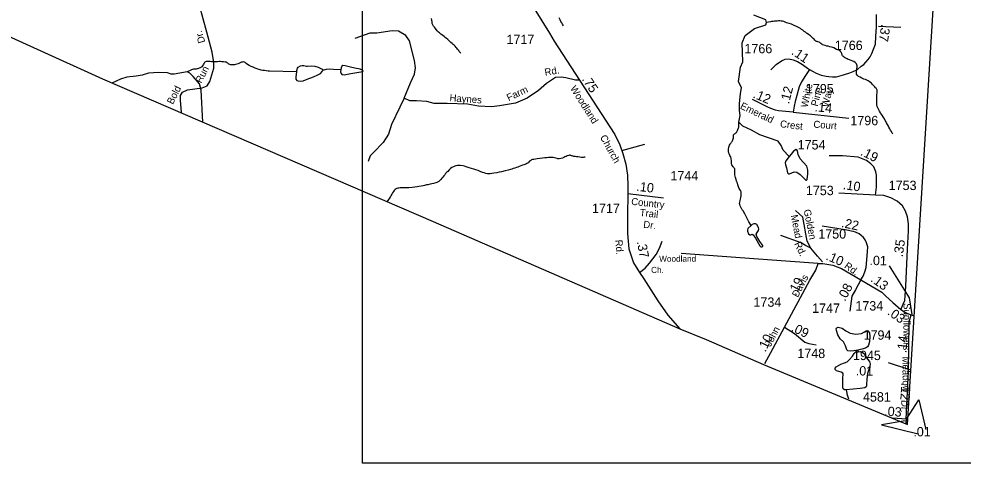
# Model space of a CAD drawing. Extents: x 2056842 to 2160602, y 826753 to 1016856.
# Drawn here: x 2121968 to 2134581, y 826753 to 832686 of the extents above; entities that cross this region are included whole.
import ezdxf

# ---------------------------------------------------------------- set-up
doc = ezdxf.new("R2010")
doc.units = 0
for name, color, linetype in [('Exist Boundary Political CountyLine', 7, 'Continuous'), ('Exist Cultural Church with Cemetery Label', 7, 'Continuous'), ('Exist Hydrographic Creek Single Shore', 7, 'Continuous'), ('Exist Hydrographic Misc Water Feature', 7, 'Continuous'), ('Exist Road Non-System Type 51', 7, 'Continuous'), ('Exist Road Non-System Type 51 Label', 7, 'Continuous'), ('Exist Road Secondary Mileage Hundredths English Label', 7, 'Continuous'), ('Exist Road Secondary Type 51 Attributed', 7, 'Continuous'), ('Exist Road Secondary Type 51 Label', 7, 'Continuous'), ('Exist Road Secondary Type 51 Number Label', 7, 'Continuous'), ('Map Preparation Inset Cut Line', 7, 'Continuous')]:
    doc.layers.add(name, color=color, linetype=linetype)

msp = doc.modelspace()

# ---------------------------------------------------------------- linework, layer by layer
at = {"layer": 'Exist Boundary Political CountyLine'}
for points in [[(2133839, 827270), (2134339, 835334), (2134342, 841203), (2134508, 848638), (2140998, 864498)], [(2133839, 827270), (2134339, 835334), (2134342, 841203), (2134508, 848638)], [(2102162, 841869), (2110170, 837921), (2110937, 837538), (2113401, 836382), (2113845, 836166), (2114325, 835934), (2116216, 835033), (2117013, 834658), (2117168, 834573), (2123083, 831884), (2127502, 829978), (2130799, 828548), (2131147, 828402), (2131915, 828068), (2133839, 827270)]]:
    msp.add_lwpolyline(points, dxfattribs=at)
at = {"layer": 'Exist Hydrographic Creek Single Shore'}
for points in [[(2127710, 832397), (2127697, 832409), (2127675, 832429), (2127663, 832440), (2127655, 832446), (2127647, 832452), (2127633, 832464), (2127613, 832476), (2127603, 832484), (2127587, 832498), (2127575, 832510), (2127557, 832529), (2127534, 832556), (2127518, 832577), (2127508, 832591), (2127496, 832609), (2127490, 832623), (2127490, 832631), (2127488, 832647), (2127483, 832670), (2127479, 832693)], [(2129243, 832594), (2129229, 832617), (2129219, 832634), (2129208, 832652), (2129198, 832674), (2129184, 832702)], [(2132256, 830847), (2132179, 830931), (2132152, 830994), (2132110, 831051), (2131864, 831136), (2131756, 831199), (2131639, 831253), (2131584, 831308), (2131602, 831394), (2131592, 831464), (2131596, 831552), (2131608, 831690), (2131620, 831766), (2131579, 831850), (2131607, 832043), (2131637, 832112), (2131629, 832366), (2131669, 832463), (2131795, 832557), (2131945, 832609), (2131954, 832640), (2131944, 832675), (2131786, 832734)], [(2132633, 832384), (2132625, 832385), (2132616, 832388), (2132611, 832392), (2132607, 832396), (2132601, 832404), (2132591, 832414), (2132580, 832424), (2132568, 832435), (2132560, 832444), (2132542, 832459), (2132530, 832467), (2132516, 832477), (2132500, 832489), (2132488, 832497), (2132474, 832509), (2132460, 832520), (2132440, 832535), (2132424, 832546), (2132407, 832556), (2132383, 832570), (2132354, 832586), (2132323, 832599), (2132289, 832614), (2132257, 832624), (2132223, 832634), (2132203, 832643), (2132187, 832650), (2132169, 832656), (2132153, 832658), (2132133, 832660), (2132117, 832660), (2132097, 832658), (2132061, 832655), (2132044, 832653), (2132023, 832651), (2132009, 832649), (2131954, 832640)], [(2127871, 832230), (2127855, 832248), (2127851, 832252), (2127843, 832264), (2127835, 832274), (2127826, 832284), (2127817, 832295), (2127808, 832306), (2127794, 832321), (2127784, 832334), (2127770, 832345), (2127754, 832359), (2127740, 832371), (2127724, 832385), (2127710, 832397)], [(2133644, 831149), (2133633, 831162), (2133623, 831181), (2133613, 831198), (2133603, 831217), (2133591, 831241), (2133585, 831255), (2133572, 831275), (2133560, 831296), (2133552, 831310), (2133542, 831328), (2133530, 831352), (2133514, 831377), (2133499, 831400), (2133483, 831423), (2133477, 831433), (2133465, 831452), (2133454, 831471), (2133443, 831497), (2133434, 831517), (2133430, 831537), (2133428, 831547), (2133428, 831562), (2133430, 831577), (2133431, 831611), (2133431, 831643), (2133431, 831663), (2133435, 831707), (2133435, 831722), (2133432, 831735), (2133428, 831745), (2133418, 831759), (2133412, 831767), (2133404, 831777), (2133394, 831788), (2133382, 831803), (2133368, 831816), (2133356, 831828), (2133344, 831836), (2133328, 831848), (2133315, 831857), (2133296, 831867), (2133276, 831875), (2133253, 831883), (2133227, 831894), (2133205, 831906), (2133183, 831919), (2133167, 831933), (2133159, 831947), (2133156, 831960), (2133156, 831971), (2133156, 831979), (2133158, 832001), (2133160, 832013), (2133162, 832027), (2133164, 832035), (2133166, 832047), (2133166, 832060), (2133162, 832073), (2133157, 832084), (2133149, 832094), (2133139, 832105), (2133123, 832115), (2133109, 832121), (2133087, 832129), (2133063, 832138), (2133047, 832146), (2133031, 832152), (2133013, 832162), (2132999, 832170), (2132986, 832178), (2132976, 832187), (2132971, 832193), (2132967, 832201), (2132964, 832207), (2132962, 832215), (2132960, 832223), (2132956, 832235), (2132950, 832244), (2132942, 832254), (2132934, 832261), (2132922, 832267), (2132907, 832273), (2132894, 832279), (2132876, 832286), (2132854, 832298), (2132839, 832304), (2132821, 832309), (2132802, 832314), (2132778, 832320), (2132760, 832323), (2132738, 832329), (2132719, 832335), (2132703, 832341), (2132695, 832347), (2132681, 832359), (2132669, 832369), (2132657, 832376), (2132641, 832382), (2132633, 832384)], [(2131749, 829925), (2131721, 829974), (2131703, 830010), (2131690, 830031), (2131676, 830064), (2131666, 830084), (2131641, 830123), (2131632, 830137), (2131622, 830152), (2131601, 830191), (2131597, 830206), (2131595, 830221), (2131597, 830239), (2131601, 830257), (2131606, 830282), (2131612, 830301), (2131616, 830321), (2131618, 830347), (2131618, 830365), (2131615, 830375), (2131607, 830395), (2131599, 830409), (2131591, 830421), (2131581, 830443), (2131573, 830469), (2131566, 830491), (2131556, 830521), (2131550, 830540), (2131542, 830569), (2131538, 830584), (2131533, 830602), (2131531, 830622), (2131531, 830642), (2131532, 830657), (2131533, 830669), (2131531, 830682), (2131525, 830692), (2131519, 830700), (2131511, 830710), (2131501, 830724), (2131494, 830736), (2131489, 830747), (2131486, 830762), (2131486, 830772), (2131486, 830784), (2131486, 830796), (2131484, 830811), (2131482, 830824), (2131479, 830835), (2131474, 830849), (2131467, 830862), (2131461, 830876), (2131453, 830893), (2131446, 830917), (2131446, 830930), (2131446, 830945), (2131452, 830974), (2131456, 830986), (2131462, 831000), (2131468, 831012), (2131476, 831022), (2131483, 831030), (2131489, 831039), (2131496, 831047), (2131501, 831057), (2131507, 831071), (2131511, 831084), (2131513, 831098), (2131513, 831110), (2131513, 831119), (2131513, 831126), (2131513, 831130), (2131514, 831136), (2131517, 831142), (2131523, 831146), (2131529, 831150), (2131535, 831154), (2131541, 831160), (2131547, 831164), (2131554, 831170), (2131558, 831177), (2131568, 831195), (2131573, 831207), (2131581, 831233), (2131584, 831241), (2131587, 831267), (2131584, 831308)]]:
    msp.add_lwpolyline(points, dxfattribs=at)
at = {"layer": 'Exist Hydrographic Misc Water Feature'}
for points in [[(2125676, 831978), (2125317, 831989), (2125299, 831990), (2125271, 831993), (2125251, 831995), (2125228, 831999), (2125203, 832002), (2125176, 832009), (2125158, 832015), (2125136, 832024), (2125122, 832030), (2125099, 832041), (2125072, 832052), (2125046, 832063), (2125024, 832075), (2125006, 832089), (2124990, 832103), (2124980, 832110), (2124970, 832113), (2124962, 832113), (2124950, 832110), (2124943, 832108), (2124934, 832105), (2124916, 832094), (2124896, 832086), (2124879, 832080), (2124862, 832076), (2124847, 832074), (2124830, 832072), (2124812, 832071), (2124796, 832071), (2124784, 832075), (2124772, 832082), (2124760, 832093), (2124750, 832100), (2124742, 832107), (2124734, 832111), (2124724, 832110), (2124700, 832112), (2124678, 832114), (2124658, 832116), (2124642, 832116), (2124620, 832114), (2124596, 832113), (2124568, 832113), (2124542, 832113), (2124522, 832115), (2124500, 832116), (2124482, 832117), (2124469, 832117), (2124459, 832113), (2124452, 832107), (2124448, 832102), (2124444, 832096), (2124436, 832082), (2124428, 832072), (2124411, 832047), (2124405, 832042), (2124399, 832038), (2124390, 832034), (2124377, 832027), (2124365, 832023), (2124350, 832018), (2124338, 832015), (2124326, 832015), (2124312, 832013), (2124299, 832013), (2124287, 832011), (2124272, 832007), (2124257, 831998), (2124215, 831977)], [(2125676, 831978), (2125667, 831914), (2125668, 831883), (2125680, 831864), (2125697, 831857), (2125728, 831855), (2125765, 831860), (2125820, 831880), (2125904, 831913), (2125960, 831939), (2125995, 831959), (2126018, 831983), (2126028, 832001)], [(2125676, 831978), (2125689, 832026), (2125698, 832040), (2125729, 832059), (2125754, 832066), (2125775, 832062), (2125808, 832054), (2125824, 832055), (2125873, 832061), (2125921, 832056), (2125966, 832043), (2126017, 832016), (2126028, 832001)], [(2126028, 832001), (2126075, 832014), (2126112, 832018), (2126170, 832016), (2126269, 832010)], [(2126269, 832010), (2126266, 831977), (2126271, 831955), (2126283, 831943), (2126311, 831937), (2126400, 831958), (2126484, 831972), (2126537, 831980), (2126563, 831984), (2126565, 831992), (2126559, 832000), (2126525, 832014), (2126457, 832029), (2126396, 832040), (2126326, 832061), (2126297, 832063), (2126283, 832057), (2126272, 832031), (2126269, 832010)], [(2124424, 831305), (2124405, 831733), (2124379, 831818), (2124296, 831915), (2124252, 831961), (2124215, 831977), (2124044, 831948), (2124002, 831949), (2123951, 831967), (2123834, 831971), (2123699, 831962), (2123613, 831936), (2123535, 831922), (2123408, 831907), (2123324, 831882), (2123208, 831830)], [(2129533, 830843), (2129527, 830840), (2129517, 830838), (2129507, 830837), (2129496, 830836), (2129482, 830836), (2129461, 830838), (2129435, 830842), (2129415, 830844), (2129397, 830847), (2129383, 830850), (2129371, 830853), (2129359, 830856), (2129350, 830859), (2129341, 830862), (2129333, 830865), (2129322, 830865), (2129314, 830863), (2129293, 830855), (2129277, 830849), (2129262, 830843), (2129247, 830836), (2129229, 830828), (2129209, 830822), (2129185, 830818), (2129167, 830819), (2129159, 830822), (2129141, 830825), (2129121, 830829), (2129105, 830833), (2129089, 830835), (2129065, 830834), (2129041, 830834), (2129019, 830832), (2128993, 830830), (2128963, 830826), (2128927, 830822), (2128893, 830818), (2128867, 830813), (2128845, 830809), (2128828, 830807), (2128817, 830803), (2128805, 830796), (2128789, 830784), (2128780, 830774), (2128772, 830766), (2128766, 830760), (2128754, 830754), (2128740, 830748), (2128714, 830739), (2128696, 830733), (2128674, 830724), (2128652, 830715), (2128632, 830706), (2128616, 830701), (2128594, 830694), (2128572, 830686), (2128551, 830680), (2128533, 830674), (2128503, 830666), (2128463, 830657), (2128415, 830645), (2128385, 830638), (2128351, 830632), (2128312, 830624), (2128285, 830620), (2128265, 830616), (2128247, 830615), (2128226, 830617), (2128207, 830621), (2128183, 830628), (2128159, 830636), (2128131, 830649), (2128101, 830660), (2128071, 830672), (2128047, 830680), (2128013, 830690), (2127985, 830699), (2127945, 830712), (2127921, 830720), (2127904, 830724), (2127862, 830730), (2127842, 830730), (2127828, 830730), (2127805, 830725), (2127793, 830721), (2127774, 830712), (2127752, 830700), (2127735, 830687), (2127717, 830668), (2127697, 830648), (2127685, 830638), (2127669, 830620), (2127656, 830604), (2127644, 830588), (2127630, 830572), (2127618, 830557), (2127604, 830541), (2127591, 830528), (2127577, 830516)], [(2132256, 830847), (2132213, 830789), (2132206, 830765), (2132208, 830739), (2132223, 830696), (2132236, 830628), (2132247, 830618), (2132262, 830617), (2132325, 830643), (2132358, 830641), (2132406, 830610), (2132479, 830531), (2132488, 830531), (2132499, 830541), (2132506, 830617), (2132508, 830665), (2132494, 830718), (2132447, 830769), (2132405, 830819), (2132379, 830873), (2132370, 830926), (2132362, 830936), (2132350, 830940), (2132317, 830921), (2132283, 830878), (2132256, 830847)], [(2127577, 830516), (2127567, 830509), (2127553, 830503), (2127537, 830497), (2127507, 830488), (2127485, 830485), (2127461, 830478), (2127431, 830472), (2127415, 830468), (2127387, 830461), (2127367, 830458), (2127341, 830453), (2127311, 830447), (2127288, 830443), (2127258, 830437), (2127222, 830432), (2127178, 830430), (2127148, 830429), (2127111, 830429), (2127077, 830429), (2127061, 830429), (2127043, 830426), (2127029, 830424), (2127018, 830421), (2127008, 830416), (2126996, 830408), (2126986, 830400), (2126980, 830394), (2126971, 830382), (2126960, 830364), (2126951, 830344), (2126943, 830332), (2126931, 830312), (2126919, 830291), (2126907, 830275), (2126895, 830259), (2126884, 830244)], [(2131749, 829925), (2131707, 829885), (2131701, 829870), (2131701, 829852), (2131716, 829816), (2131734, 829801), (2131745, 829801), (2131765, 829809), (2131776, 829802), (2131808, 829758), (2131865, 829654), (2131881, 829642), (2131895, 829641), (2131905, 829651), (2131904, 829661), (2131864, 829711), (2131824, 829778), (2131818, 829810), (2131829, 829832), (2131846, 829858), (2131853, 829880), (2131848, 829901), (2131824, 829940), (2131809, 829947), (2131786, 829949), (2131765, 829941), (2131749, 829925)], [(2133174, 828263), (2133121, 828251), (2133075, 828246), (2133041, 828252), (2133030, 828265), (2133008, 828321), (2132984, 828372), (2132938, 828415), (2132910, 828465), (2132891, 828525), (2132887, 828551), (2132893, 828561), (2132913, 828568), (2132964, 828554), (2133015, 828520), (2133071, 828487), (2133149, 828476), (2133222, 828485), (2133296, 828523), (2133308, 828519), (2133330, 828493), (2133336, 828443), (2133333, 828379), (2133318, 828327), (2133303, 828306), (2133277, 828288), (2133227, 828277), (2133174, 828263)], [(2133020, 827733), (2132996, 827733), (2132980, 827743), (2132974, 827754), (2132973, 827783), (2132976, 827889), (2132978, 827943), (2132973, 827955), (2132954, 827967), (2132892, 827985), (2132873, 828005), (2132872, 828020), (2132884, 828039), (2132946, 828075), (2132998, 828092), (2133031, 828107), (2133064, 828135), (2133104, 828181), (2133124, 828219), (2133145, 828235), (2133179, 828241)], [(2133179, 828241), (2133210, 828242), (2133235, 828234), (2133267, 828208), (2133286, 828168), (2133306, 828142), (2133331, 828109), (2133339, 828076), (2133336, 828049), (2133320, 828002), (2133306, 827949), (2133294, 827872), (2133292, 827801), (2133292, 827783), (2133287, 827771), (2133268, 827757), (2133207, 827749), (2133020, 827733)], [(2133174, 828263), (2133179, 828241)], [(2133020, 827733), (2133029, 827687), (2133030, 827677), (2133033, 827667), (2133037, 827653), (2133041, 827639), (2133051, 827615), (2133053, 827610)]]:
    msp.add_lwpolyline(points, dxfattribs=at)
at = {"layer": 'Exist Road Non-System Type 51'}
for p, q in [((2133451, 832587), (2133750, 832575)), ((2130023, 830928), (2130328, 831012))]:
    msp.add_line(p, q, dxfattribs=at)
for points in [[(2124138, 831434), (2124125, 831599), (2124127, 831661), (2124152, 831707), (2124219, 831740), (2124414, 831765), (2124482, 831794), (2124520, 831848), (2124571, 832030), (2124573, 832103), (2124548, 832240), (2124477, 832510), (2124382, 832867)], [(2127116, 831628), (2127200, 831831), (2127252, 831947), (2127267, 832033), (2127254, 832130), (2127186, 832392), (2127138, 832463), (2127038, 832521), (2126955, 832529), (2126751, 832495), (2126655, 832495), (2126456, 832424)], [(2129459, 831867), (2129404, 831868), (2129275, 831900), (2129211, 831906), (2129134, 831904), (2129016, 831825), (2128910, 831729), (2128758, 831629), (2128600, 831561), (2128388, 831527), (2128280, 831511), (2128106, 831521), (2127959, 831546), (2127691, 831557), (2127515, 831558), (2127417, 831583), (2127280, 831591), (2127191, 831591), (2127116, 831628)], [(2127116, 831628), (2127055, 831509), (2126947, 831274), (2126905, 831145), (2126832, 831036), (2126703, 830903), (2126659, 830859), (2126634, 830780)], [(2132549, 829622), (2132497, 829717), (2132439, 830039), (2132341, 830125)], [(2132549, 829622), (2132476, 829659), (2132416, 829694), (2132146, 829792)], [(2130257, 829301), (2130332, 829356), (2130391, 829424), (2130481, 829538), (2130526, 829622), (2130562, 829717)], [(2132701, 829443), (2132634, 829518), (2132549, 829622)], [(2132644, 829417), (2132214, 829451), (2130813, 829552)]]:
    msp.add_lwpolyline(points, dxfattribs=at)
at = {"layer": 'Exist Road Secondary Mileage Hundredths English Label'}
msp.add_line((2133868, 827999), (2133585, 828092), dxfattribs=at)
for points in [[(2133902, 828740), (2133864, 828961), (2133599, 829387)], [(2133830, 827350), (2133989, 827600), (2134083, 827204)], [(2133808, 827317), (2133491, 827262), (2133982, 827145)]]:
    msp.add_lwpolyline(points, dxfattribs=at)
at = {"layer": 'Exist Road Secondary Type 51 Attributed'}
for p, q in [((2132309, 831439), (2133056, 831359)), ((2130101, 830354), (2130578, 830297)), ((2133410, 830334), (2132920, 830360)), ((2133821, 827341), (2133850, 827979)), ((2133821, 827341), (2133641, 827352)), ((2133821, 827341), (2133817, 827280))]:
    msp.add_line(p, q, dxfattribs=at)
for points in [[(2128273, 833799), (2128362, 833671), (2128458, 833532), (2128526, 833413), (2128623, 833239), (2128714, 833077), (2128790, 832933), (2128851, 832826), (2129057, 832497), (2129120, 832391), (2129459, 831867), (2129928, 831143), (2129996, 831002), (2130037, 830889), (2130074, 830745), (2130099, 830600), (2130103, 830454), (2130101, 830354)], [(2132531, 832012), (2132571, 831986), (2132619, 831960), (2132686, 831933), (2132750, 831920), (2132789, 831916), (2132835, 831911), (2132892, 831914), (2132952, 831929), (2132998, 831943), (2133069, 831968), (2133114, 831985), (2133172, 832012), (2133220, 832054), (2133253, 832077), (2133281, 832108), (2133315, 832142), (2133339, 832180), (2133364, 832222), (2133385, 832283), (2133409, 832349), (2133417, 832449), (2133426, 832582), (2133424, 832744)], [(2132014, 832008), (2132084, 832079), (2132154, 832124), (2132203, 832148), (2132255, 832154), (2132311, 832140), (2132367, 832116), (2132435, 832075), (2132504, 832029), (2132531, 832012)], [(2132531, 832012), (2132466, 831915), (2132454, 831894), (2132423, 831845), (2132393, 831781), (2132377, 831732), (2132359, 831665), (2132339, 831583), (2132326, 831521), (2132309, 831439)], [(2132309, 831439), (2132113, 831459), (2132074, 831469), (2132015, 831489), (2131964, 831511), (2131766, 831611)], [(2133410, 830334), (2133425, 830437), (2133425, 830531), (2133425, 830598), (2133414, 830645), (2133389, 830712), (2133348, 830751), (2133291, 830797), (2133179, 830838), (2132971, 830855), (2132790, 830859)], [(2130101, 830354), (2130096, 830060), (2130098, 829821), (2130118, 829615), (2130177, 829427), (2130257, 829301), (2130317, 829213), (2130503, 828919), (2130637, 828729), (2130799, 828548)], [(2133749, 828806), (2133782, 828875), (2133802, 828925), (2133808, 828988), (2133814, 829118), (2133839, 829611), (2133853, 829853), (2133850, 829951), (2133838, 830044), (2133811, 830116), (2133770, 830190), (2133699, 830253), (2133618, 830298), (2133521, 830329), (2133410, 830334)], [(2133217, 829201), (2133248, 829252), (2133270, 829307), (2133285, 829367), (2133297, 829468), (2133306, 829581), (2133307, 829643), (2133291, 829693), (2133273, 829735), (2133250, 829767), (2133220, 829795), (2133192, 829816), (2133145, 829837), (2133111, 829848), (2133006, 829867), (2132697, 829918)], [(2132197, 828569), (2132533, 829197), (2132612, 829331), (2132644, 829417), (2132706, 829420), (2132843, 829399), (2132956, 829351), (2133217, 829201)], [(2133217, 829201), (2133142, 829067), (2133095, 828982), (2133070, 828782)], [(2133217, 829201), (2133495, 829035), (2133551, 828982), (2133643, 828896), (2133749, 828806)], [(2133749, 828806), (2133783, 828781), (2133830, 828754), (2133887, 828732)], [(2133850, 827979), (2133861, 828616), (2133868, 828670), (2133887, 828732)], [(2133887, 828732), (2133929, 828720)], [(2131934, 828084), (2132015, 828231), (2132197, 828569)], [(2132197, 828569), (2132329, 828485), (2132469, 828368), (2132520, 828349), (2132619, 828334)], [(2133850, 827979), (2133883, 827978)], [(2133821, 827341), (2133844, 827338)]]:
    msp.add_lwpolyline(points, dxfattribs=at)
at = {"layer": 'Map Preparation Inset Cut Line'}
msp.add_lwpolyline([(2126559, 840801), (2135708, 840801), (2135708, 826753), (2126559, 826753)], close=True, dxfattribs=at)

# ---------------------------------------------------------------- texts
at = {"layer": 'Exist Cultural Church with Cemetery Label'}
for s, p in [('Woodland', (2130521, 829442)), ('Ch.', (2130413, 829292))]:
    msp.add_text(s, height=82, dxfattribs=at).set_placement(p)
at = {"layer": 'Exist Road Non-System Type 51 Label'}
for s, rotation, p in [('Dr.', 107.6445, (2124459, 832378)), ('Run', 62.2527, (2124403, 831819)), ('Rd.', 10.1274, (2128999, 831925)), ('Bold', 62.9967, (2124024, 831536)), ('Farm', 25.3847, (2128511, 831585)), ('Haynes', 355.8284, (2127719, 831587)), ('Golden', 281.2431, (2132451, 830133)), ('Mead', 281.2431, (2132278, 830060)), ('Rd.', 295.4414, (2132323, 829683))]:
    msp.add_text(s, height=95, rotation=rotation, dxfattribs=at).set_placement(p)
at = {"layer": 'Exist Road Secondary Mileage Hundredths English Label'}
for s, rotation, p in [('.37', 260.9065, (2133490, 832622)), ('.11', 325.8265, (2132279, 832220)), ('.75', 302.8898, (2129484, 831881)), ('.12', 75.7697, (2132255, 831543)), ('.12', 336.791, (2131765, 831638)), ('.14', 353.9239, (2132594, 831454)), ('.19', 333.4437, (2133199, 830872)), ('.10', 353.1624, (2130212, 830391)), ('.10', 351.6774, (2132971, 830414)), ('.22', 348.1032, (2132947, 829907)), ('.35', 81.631, (2133774, 829501)), ('.37', 280.9154, (2130222, 829711)), ('.10', 336.9274, (2132738, 829474)), ('.01', 359.4539, (2133330, 829398)), ('.19', 61.8167, (2132345, 828985)), ('.13', 324.3593, (2133336, 829187)), ('.08', 62.3282, (2133003, 828906)), ('.03', 324.5331, (2133561, 828745)), ('.09', 334.5485, (2132274, 828521)), ('.10', 63.9974, (2131940, 828228)), ('.14', 84.514, (2133823, 828219)), ('.01', 359.4539, (2133147, 827924)), ('.12', 266.4213, (2133757, 827829)), ('.03', 356.1236, (2133524, 827387)), ('.01', 0.5242, (2133917, 827109))]:
    msp.add_text(s, height=125, rotation=rotation, dxfattribs=at).set_placement(p)
at = {"layer": 'Exist Road Secondary Type 51 Label'}
for s, rotation, p in [('Woodland', 302.5072, (2129327, 831759)), ('White', 77.9397, (2132504, 831496)), ('Pine', 74.8051, (2132637, 831511)), ('Way', 76.7744, (2132780, 831501)), ('Emerald', 334.5419, (2131595, 831492)), ('Crest', 353.1222, (2132132, 831240)), ('Court', 355.5958, (2132579, 831234)), ('Church', 298.99, (2129727, 831106)), ('Country', 353.5922, (2130144, 830204)), ('Trail', 353.5225, (2130258, 830055)), ('Dr.', 353.1398, (2130305, 829897)), ('Rd.', 274.4354, (2129935, 829733)), ('Rd.', 324.3746, (2132986, 829368)), ('Davis', 62.328, (2132373, 828959)), ('Sunflowers', 269.6315, (2133786, 828889)), ('John', 62.3282, (2132009, 828301)), ('Meadow', 270.9867, (2133768, 828175)), ('Dr.', 267.8152, (2133758, 827597))]:
    msp.add_text(s, height=95, rotation=rotation, dxfattribs=at).set_placement(p)
at = {"layer": 'Exist Road Secondary Type 51 Number Label'}
for s, p in [('1717', (2128482, 832350)), ('1766', (2132868, 832271)), ('1766', (2131660, 832227)), ('1795', (2132481, 831692)), ('1796', (2133075, 831266)), ('1754', (2132371, 830942)), ('1744', (2130671, 830528)), ('1753', (2133587, 830400)), ('1753', (2132481, 830332)), ('1717', (2129624, 830093)), ('1750', (2132647, 829752)), ('1734', (2131781, 828841)), ('1747', (2132565, 828760)), ('1734', (2133142, 828791)), ('1794', (2133252, 828401)), ('1748', (2132367, 828156)), ('1945', (2133110, 828129)), ('4581', (2133244, 827575))]:
    msp.add_text(s, height=125, dxfattribs=at).set_placement(p)

doc.saveas('drawing.dxf')
